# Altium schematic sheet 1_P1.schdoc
size 601 x 429 mm; Symbol: Sheet-Symbol_A4; Device: Sheet-Symbol_A4; Company: 嘉立创EDA; Version: V1.0; Page Size: A4; @Project Name: F407DCMI+AD9226; @Page Count: 1; @Update Date: 2024-08-18; @Create Date: 2024-08-13; @Schematic Name: Schematic1; @Page No: 1; @Page Name: P1; @Create Time: 14:49:27; @Update Time: 01:13:08; Width: 2338; Height: 1652; Region Start: 1; X Region Count: 6; Y Region Count: 4; Blade Width: 10; Title Block Position: 3; @Board Name: Board1
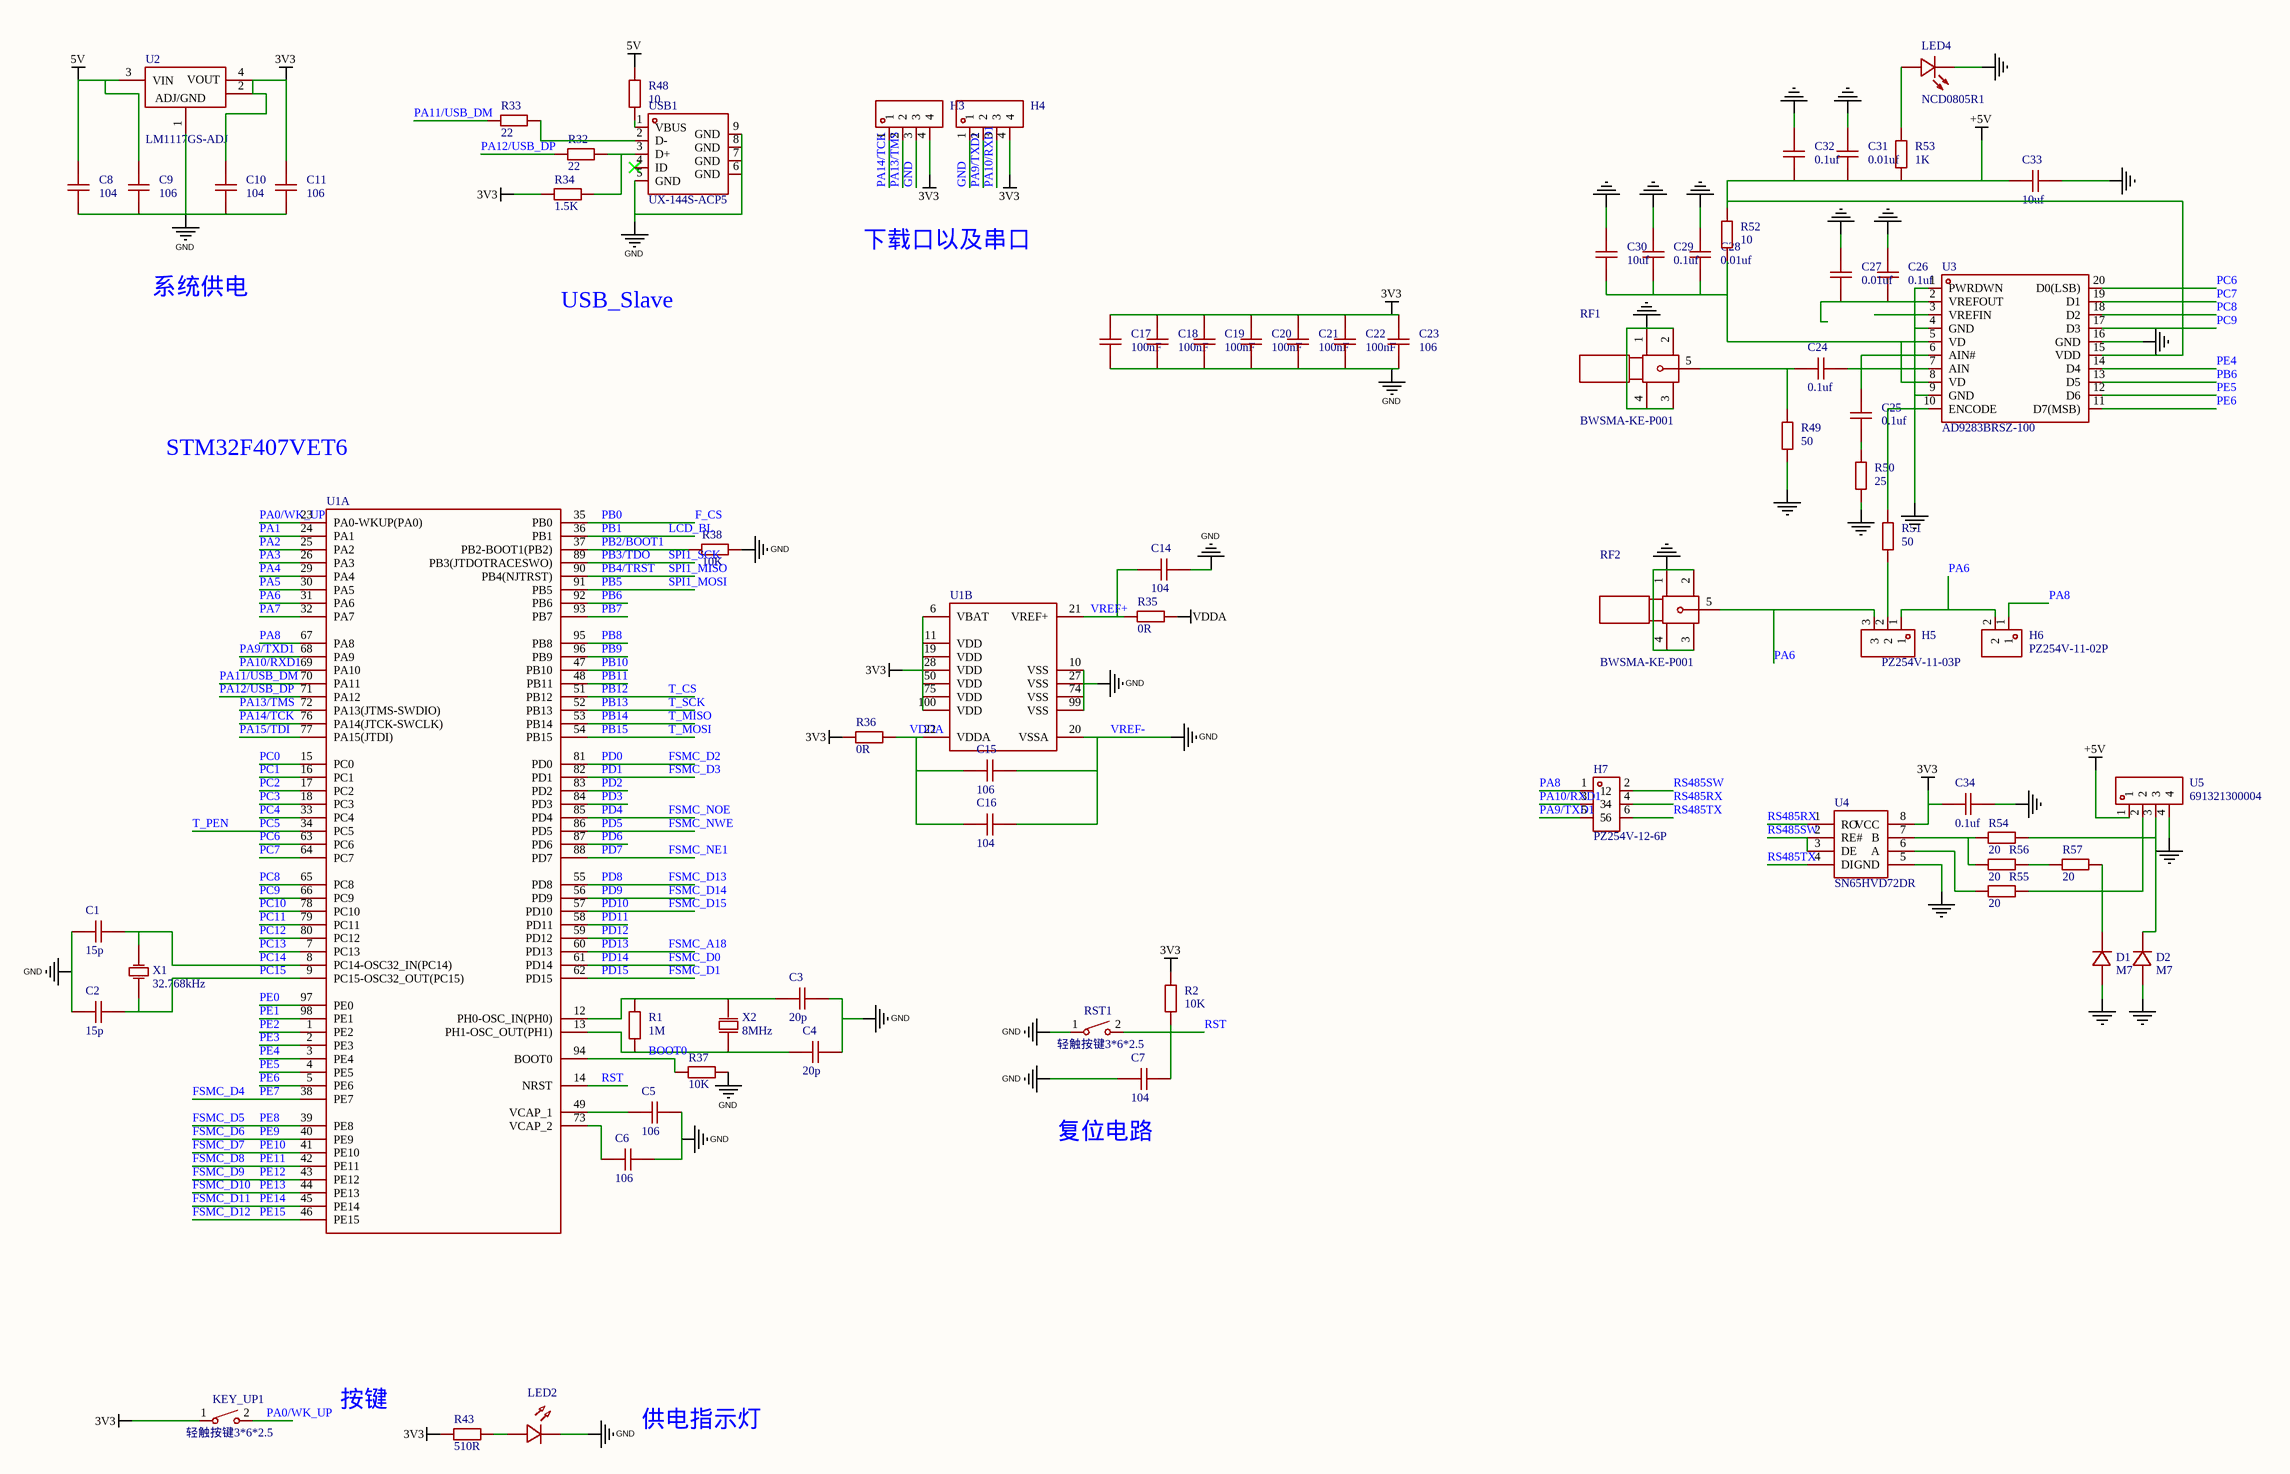
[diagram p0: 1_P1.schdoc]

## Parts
C1  15p  [C0805]  (value not drawn)
C2  15p  [C0805]  (value not drawn)
C3  20p  [C0805]  (value not drawn)
C4  20p  [C0805]  (value not drawn)
C5  106  [C0805]  (value not drawn)
C6  106  [C0805]  (value not drawn)
C7  104  [C0805]  (value not drawn)
C8  104  [C0805]  (value not drawn)
C9  106  [C0805]  (value not drawn)
C10  104  [C0805]  (value not drawn)
C11  106  [C0805]  (value not drawn)
C14  104  [C0805]  (value not drawn)
C15  106  [C0805]  (value not drawn)
C16  104  [C0805]  (value not drawn)
C17  100nF  [C0805]  (value not drawn)
C18  100nF  [C0805]  (value not drawn)
C19  100nF  [C0805]  (value not drawn)
C20  100nF  [C0805]  (value not drawn)
C21  100nF  [C0805]  (value not drawn)
C22  100nF  [C0805]  (value not drawn)
C23  106  [C0805]  (value not drawn)
C24  0.1uf  [C0805]  (value not drawn)
C25  0.1uf  [C0805]  (value not drawn)
C26  0.1uf  [C0805]  (value not drawn)
C27  0.01uf  [C0805]  (value not drawn)
C28  0.01uf  [C0805]  (value not drawn)
C29  0.1uf  [C0805]  (value not drawn)
C30  10uf  [C0805]  (value not drawn)
C31  0.01uf  [C0805]  (value not drawn)
C32  0.1uf  [C0805]  (value not drawn)
C33  10uf  [C0805]  (value not drawn)
C34  0.1uf  [C0805]  (value not drawn)
D1  M7  [SMA_L4.3-W2.6-LS5.2-RD]  (value not drawn)
D2  M7  [SMA_L4.3-W2.6-LS5.2-RD]  (value not drawn)
H3  2.54-1*4P反弯排针  [HDR-TH_4P-P2.54-H-M-W10.4]  (value not drawn)
H4  2.54-1*4P反弯排针  [HDR-TH_4P-P2.54-H-M-W10.4]  (value not drawn)
H5  PZ254V-11-03P  [HDR-TH_3P-P2.54-V-M]  (value not drawn)
H6  PZ254V-11-02P  [HDR-TH_2P-P2.54-V-M]  (value not drawn)
H7  PZ254V-12-6P  [HDR-TH_6P-P2.54-V-M-R2-C3-S2.54]  (value not drawn)
KEY_UP1  轻触按键3*6*2.5  [SW-SMD_L6.0-W3.6-LS8.0]  (value not drawn)
LED2  LED_0805-G  [LED_0805]  (value not drawn)
LED4  NCD0805R1  [LED0805-R-RD]  (value not drawn)
R1  1M  [R0805]  (value not drawn)
R2  10K  [R0805]  (value not drawn)
R32  22  [R0805]  (value not drawn)
R33  22  [R0805]  (value not drawn)
R34  1.5K  [R0805]  (value not drawn)
R35  0R  [R0805]  (value not drawn)
R36  0R  [R0805]  (value not drawn)
R37  10K  [R0805]  (value not drawn)
R38  10K  [R0805]  (value not drawn)
R43  510R  [R0805]  (value not drawn)
R48  10  [R0805]  (value not drawn)
R49  50  [R0805]  (value not drawn)
R50  25  [R0805]  (value not drawn)
R51  50  [R0805]  (value not drawn)
R52  10  [R0805]  (value not drawn)
R53  1K  [R0805]  (value not drawn)
R54  20  [R0805]  (value not drawn)
R55  20  [R0805]  (value not drawn)
R56  20  [R0805]  (value not drawn)
R57  20  [R0805]  (value not drawn)
RF1  BWSMA-KE-P001  [SMA-SMD_BWSMA-KE-P001]  (value not drawn)
RF2  BWSMA-KE-P001  [SMA-SMD_BWSMA-KE-P001]  (value not drawn)
RST1  轻触按键3*6*2.5  [SW-SMD_L6.0-W3.6-LS8.0]  (value not drawn)
U1  STM32F407VET6  [LQFP-100_L14.0-W14.0-P0.50-LS16.0-BL]  (value not drawn)  (parts A,B of 2)
U2  LM1117GS-ADJ  [SOT-223-3_L6.5-W3.4-P2.30-LS7.0-BR]  (value not drawn)
U3  AD9283BRSZ-100  [SSOP-20_L7.2-W5.3-P0.65-LS7.8-BL]  (value not drawn)
U4  SN65HVD72DR  [SOIC-8_L5.0-W4.0-P1.27-LS6.0-BL]  (value not drawn)
U5  691321300004  [CONN-TH_4P-P3.81_691321300004]  (value not drawn)
USB1  UX-144S-ACP5  [MINI-USB-SMD_UX-144S-ACP5]  (value not drawn)
X1  32.768kHz  [OSC-TH_BD3.1-P0.8-D0.3]  (value not drawn)
X2  8MHz  [CRYSTAL-SMD_L11.5-W4.8-LS12.7]  (value not drawn)

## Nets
3V3: C10.2 C11.2 C17.2 C18.2 C19.2 C20.2 C21.2 C22.2 C23.2 C34.1 H3.4 H4.4 KEY_UP1.1 R2.2 R34.1 R36.1 R43.1 U1.6(VBAT) U1.11(VDD) U1.19(VDD) U1.28(VDD) U1.50(VDD) U1.75(VDD) U1.100(VDD) U2.2(VOUT) U2.4(VOUT) U4.8(VCC)
5V: C8.2 C9.2 R48.1 U2.3(VIN)
+5V: C31.1 C32.1 C33.1 R52.2 R53.1 U3.15(VDD) U5.1
GND: C1.1 C2.1 C3.2 C4.2 C5.2 C6.2 C7.1 C8.1 C9.1 C10.1 C11.1 C14.2 C15.2 C16.2 C17.1 C18.1 C19.1 C20.1 C21.1 C22.1 C23.1 C26.2 C27.2 C28.2 C29.2 C30.2 C31.2 C32.2 C33.2 C34.2 D1.2(A) D2.2(A) H3.3 H4.1 LED2.1(C) LED4.2(-) R37.2 R38.2 R49.1 R50.1 RF1.1 RF1.2 RF1.3 RF1.4 RF2.1 RF2.2 RF2.3 RF2.4 RST1.1 U1.10(VSS) U1.20(VSSA) U1.27(VSS) U1.74(VSS) U1.99(VSS) U2.1(GND) U3.1(PWRDWN) U3.4(GND) U3.9(GND) U3.16(GND) U4.5(GND) U5.4 USB1.5(GND) USB1.6(GND) USB1.7(GND) USB1.8(GND) USB1.9(GND)  [also labelled VREF-]
VDDA: C15.1 C16.1 R35.2 R36.2 U1.22(VDDA)
BOOT0: R37.1 U1.94(BOOT0)
F_CS: U1.35(PB0)  [also labelled PB0]
FSMC_A18: U1.60(PD13)  [also labelled PD13]
FSMC_D0: U1.61(PD14)  [also labelled PD14]
FSMC_D1: U1.62(PD15)  [also labelled PD15]
FSMC_D2: U1.81(PD0)  [also labelled PD0]
FSMC_D3: U1.82(PD1)  [also labelled PD1]
FSMC_D4: U1.38(PE7)  [also labelled PE7]
FSMC_D5: U1.39(PE8)  [also labelled PE8]
FSMC_D6: U1.40(PE9)  [also labelled PE9]
FSMC_D7: U1.41(PE10)  [also labelled PE10]
FSMC_D8: U1.42(PE11)  [also labelled PE11]
FSMC_D9: U1.43(PE12)  [also labelled PE12]
FSMC_D10: U1.44(PE13)  [also labelled PE13]
FSMC_D11: U1.45(PE14)  [also labelled PE14]
FSMC_D12: U1.46(PE15)  [also labelled PE15]
FSMC_D13: U1.55(PD8)  [also labelled PD8]
FSMC_D14: U1.56(PD9)  [also labelled PD9]
FSMC_D15: U1.57(PD10)  [also labelled PD10]
FSMC_NE1: U1.88(PD7)  [also labelled PD7]
FSMC_NOE: U1.85(PD4)  [also labelled PD4]
FSMC_NWE: U1.86(PD5)  [also labelled PD5]
LCD_BL: U1.36(PB1)  [also labelled PB1]
PA0/WK_UP: KEY_UP1.2 U1.23(PA0-WKUP(PA0))
PA1: U1.24(PA1)
PA2: U1.25(PA2)
PA3: U1.26(PA3)
PA4: U1.29(PA4)
PA5: U1.30(PA5)
PA6: H5.1 H5.3 H6.2 RF2.5 U1.31(PA6)
PA7: U1.32(PA7)
PA8: H6.1 H7.1 U1.67(PA8)
PA9/TXD1: H4.2 H7.5 U1.68(PA9)
PA10/RXD1: H4.3 H7.3 U1.69(PA10)
PA11/USB_DM: R33.2 U1.70(PA11)
PA12/USB_DP: R32.1 U1.71(PA12)
PA13/TMS: H3.2 U1.72(PA13(JTMS-SWDIO))
PA14/TCK: H3.1 U1.76(PA14(JTCK-SWCLK))
PA15/TDI: U1.77(PA15(JTDI))
PB2/BOOT1: R38.1 U1.37(PB2-BOOT1(PB2))
PB3/TDO: U1.89(PB3(JTDOTRACESWO))  [also labelled SPI1_SCK]
PB4/TRST: U1.90(PB4(NJTRST))  [also labelled SPI1_MISO]
PB5: U1.91(PB5)  [also labelled SPI1_MOSI]
PB6: U1.92(PB6) U3.13(D5)
PB7: U1.93(PB7)
PB8: U1.95(PB8)
PB9: U1.96(PB9)
PB10: U1.47(PB10)
PB11: U1.48(PB11)
PB12: U1.51(PB12)  [also labelled T_CS]
PB13: U1.52(PB13)  [also labelled T_SCK]
PB14: U1.53(PB14)  [also labelled T_MISO]
PB15: U1.54(PB15)  [also labelled T_MOSI]
PC0: U1.15(PC0)
PC1: U1.16(PC1)
PC2: U1.17(PC2)
PC3: U1.18(PC3)
PC4: U1.33(PC4)
PC5: U1.34(PC5)  [also labelled T_PEN]
PC6: U1.63(PC6) U3.20(D0(LSB))
PC7: U1.64(PC7) U3.19(D1)
PC8: U1.65(PC8) U3.18(D2)
PC9: U1.66(PC9) U3.17(D3)
PC10: U1.78(PC10)
PC11: U1.79(PC11)
PC12: U1.80(PC12)
PC13: U1.7(PC13)
PC14: C1.2 U1.8(PC14-OSC32_IN(PC14)) X1.1(OSC1)
PC15: C2.2 U1.9(PC15-OSC32_OUT(PC15)) X1.2(OSC2)
PD2: U1.83(PD2)
PD3: U1.84(PD3)
PD6: U1.87(PD6)
PD11: U1.58(PD11)
PD12: U1.59(PD12)
PE0: U1.97(PE0)
PE1: U1.98(PE1)
PE2: U1.1(PE2)
PE3: U1.2(PE3)
PE4: U1.3(PE4) U3.14(D4)
PE5: U1.4(PE5) U3.12(D6)
PE6: U1.5(PE6) U3.11(D7(MSB))
RS485RX: H7.4 U4.1(RO)
RS485SW: H7.2 U4.2(RE#) U4.3(DE)
RS485TX: H7.6 U4.4(DI)
RST: C7.2 R2.1 RST1.2 U1.14(NRST)
VREF+: C14.1 R35.1 U1.21(VREF+)
NetC3_1: C3.1 R1.2 U1.12(PH0-OSC_IN(PH0)) X2.1(OSC1)
NetC4_1: C4.1 R1.1 U1.13(PH1-OSC_OUT(PH1)) X2.2(OSC2)
NetC5_1: C5.1 U1.49(VCAP_1)
NetC6_1: C6.1 U1.73(VCAP_2)
NetC24_1: C24.1 R49.2 RF1.5
NetC24_2: C24.2 U3.7(AIN)
NetC25_1: C25.1 R50.2
NetC25_2: C25.2 U3.6(AIN#)
NetC26_1: C26.1 C27.1 U3.2(VREFOUT)
NetC28_1: C28.1 C29.1 C30.1 R52.1 U3.5(VD) U3.8(VD)
NetD1_1: D1.1(K) R55.2 R57.2 U5.2
NetD2_1: D2.1(K) R54.1 U5.3
NetH5_2: H5.2 R51.1
NetLED2_2: LED2.2(A) R43.2
NetLED4_1: LED4.1(+) R53.2
NetR32_2: R32.2 R34.2 USB1.3(D+)
NetR33_1: R33.1 USB1.2(D-)
NetR48_2: R48.2 USB1.1(VBUS)
NetR51_2: R51.2 U3.10(ENCODE)
NetR54_2: R54.2 R56.2 U4.7(B)
NetR55_1: R55.1 U4.6(A)
NetR56_1: R56.1 R57.1

Not connected (* = marked no-connect by the designer): U3 3(VREFIN); USB1 4(ID)*

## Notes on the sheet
- 下载口以及串口
- 系统供电
- USB_Slave
- STM32F407VET6
- (near C7) 复位电路
- 按键
- 供电指示灯

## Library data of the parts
C1-C11 C14-C34 = CAP_0805: Symbol: CapAcitance; Convert to PCB: yes
D1 D2 = M7_C95872: 二极管配置:独立式;正向压降(Vf):1.1V@1A;直流反向耐压(Vr):1kV;整流电流:1A;; Manufacturer: MDD(辰达半导体); Add into BOM: yes; Diode Configuration: 独立式; Reverse Voltage (Vr): 1kV; Rectified Current: 1A; Reverse Leakage Current: 5uA@1kV
H3 H4 = 2.54-1*4P反弯排针: 间距:2.54mm;总PIN位数:4;排数:1;插针结构:1x4P;行距:-;安装类型:弯插;圆针/方针:方针;额定电流:3A;额定电压:-;配合针长度:6mm;塑高:-;端接针长度:-;触头材质:-;触头镀层:-;工作温度范围:-55~+105;颜色:黑色;; Manufacturer: BOOMELE(博穆精密); Add into BOM: yes; Pitch: 2.54mm; Pin Structure: 1x4P; Circluar Pins/Square Pins: 方针; Current Rating (Max): 3A
H5 = PZ254V-11-03P: 插针结构:1x3P;间距:2.54mm;行距:-;圆针/方针:方针;安装类型:直插;排数:单排;总PIN位数:3P;额定电流:3A;额定电压:250V;配合针长度:6mm;塑高:2.5mm;端接针长度:3mm;工作温度范围:-40℃~+105℃;颜色:黑色;; Manufacturer: XFCN(兴飞); Symbol: PZ254V-11-03P_C2937625; Add into BOM: yes; Pin Structure: 1x3P; Pitch: 2.54mm; Circluar Pins/Square Pins: 方针; Current Rating (Max): 3A; Voltage Rating (Max): 250V
H6 = PZ254V-11-02P: 插针结构:1x2P;间距:2.54mm;行距:-;圆针/方针:方针;安装类型:直插;排数:单排;总PIN位数:2P;额定电流:-;额定电压:-;配合针长度:6mm;塑高:2.5mm;端接针长度:3mm;触头材质:黄铜;触头镀层:-;工作温度范围:-40℃~+105℃;颜色:黑色;; Manufacturer: XFCN(兴飞); Add into BOM: yes; Pin Structure: 1x2P; Pitch: 2.54mm; Circluar Pins/Square Pins: 方针
H7 = PZ254V-12-6P: 插针结构:2x3P;间距:2.54mm;行距:2.54mm;圆针/方针:方针;安装类型:直插;排数:双排;总PIN位数:6P;额定电流:-;额定电压:-;配合针长度:6mm;塑高:2.5mm;端接针长度:3mm;触头材质:黄铜;触头镀层:-;工作温度范围:-40℃~+105℃;颜色:黑色;; Manufacturer: XFCN(兴飞); Add into BOM: yes; Pin Structure: 2x3P; Pitch: 2.54mm; Circluar Pins/Square Pins: 方针
KEY_UP1 RST1 = 轻触按键3*6*2.5: Add into BOM: yes
LED2 = LED_0805-G: Symbol: LED_G; Convert to PCB: yes
LED4 = NCD0805R1: 灯头类型:-;发光颜色:红色;正向电压(VF):1.6V~2.6V;功率:65mW;正向电流:20mA;主波长:615nm~630nm;二极管配置:独立二极管;透镜颜色:无色透明透镜;色温:-;发光强度:67mcd~195mcd;发光角度:130°;载带方式:-;工作温度:-30℃~+85℃;; Manufacturer: 国星光电; Symbol: FC-2012HRK-620D; Add into BOM: yes; Emitted Color: 红色; Power Dissipation: 65mW; Forward Current: 20mA; Diode Configuration: 独立二极管; Lens Color: 无色透明透镜; Viewing Angle: 130°
R1 R2 R32-R38 R43 R48 = Res_0805: Symbol: 电阻; Convert to PCB: yes
R49-R57 = RC0805FR-0710KL: 电阻类型:厚膜电阻;阻值:10kΩ;精度:±1%;功率:125mW;最大工作电压:150V;温度系数:±100ppm/℃;; Manufacturer: YAGEO(国巨); Add into BOM: yes; Tolerance: ±1%; Power(Watts): 125mW; Overload Voltage (Max): 150V
RF1 RF2 = BWSMA-KE-P001: 连接器类型:板端;接口类型:内孔;端口数量:1;接口直径:5.2mm;接口长度/高度:-;频率-最大值:-;射频系列:SMA;阻抗:50Ω;样式:偏脚;工作温度范围:-;; Manufacturer: BAT WIRELESS(蝙蝠无线); Add into BOM: yes; Connector Type: 板端; Interface Type: 内孔; Number of Ports: 1; Interface Diameter: 5.2mm; RF Series: SMA; Impedance: 50Ω; Style: 偏脚
U1 = STM32F407VET6: CPU内核:ARM Cortex-M4;CPU最大主频:168MHz;工作电压范围:1.8V~3.6V;程序存储容量:512KB;程序存储器类型:FLASH;RAM总容量:192KB;GPIO端口数量:82;; Manufacturer: ST(意法半导体); Add into BOM: yes; CPU Maximum Speed: 168MHz; Program Storage Size: 512KB; Program Memory Type: FLASH; RAM Size: 192KB; GPIO Ports Number: 82; ADC (Bit): 12bit; Universal Serial Bus: 有; Peripheral/Function: DMA；LCD/LED驱动；PWM
U2 = LM1117GS-ADJ: 输出类型:-;; Manufacturer: HTC; Add into BOM: yes
U3 = AD9283BRSZ-100: 接口:并行;电源电压:2.7V~3.6V;采样率:100MHz;分辨率:8位;; Manufacturer: ADI(亚德诺); Add into BOM: yes; Interface: 并行; differential input: 是; number of channels: 1; sampling frequency: 100MHz; resolution: 8位
U4 = SN65HVD72DR: 类型:收发器;数据速率:250Kbps;驱动器/接收器:1/1;; Manufacturer: TI(德州仪器); Add into BOM: yes; Types: 收发器; Supply Voltage: 3V~3.6V; Driver/receiver: 1/1
U5 = 691321300004: Add into BOM: yes
USB1 = UX-144S-ACP5: 连接器类型:Mini-B;标准:USB 2.0;公母:母;触点数量:5P;端口数量:1;安装方式:卧贴;额定电流 - 电源:1.5A;工作温度范围:-20℃~+70℃;焊接温度(最大值):260℃;; Manufacturer: XUNPU(讯普); Add into BOM: yes; Connector Type: Mini-B; Gender: 母; Number of Contacts: 5P; Number of Ports: 1; Current Rating - Power (Max): 1.5A; Welding Temperature (Max): 260℃
X1 = X308032768KGB2SC: 晶振类型:直插晶振;频率:32.768kHz;常温频差:±10ppm;外接负载电容:12.5pF;频率稳定度(全温):-;; Manufacturer: YXC(扬兴晶振); Add into BOM: yes; Crystal Type: 直插晶振; Normal temperature Frequency Tolerance: ±10ppm; External load capacitor: 12.5pF
X2 = X49SM8MSD2SC: 晶振类型:49SMD晶振;频率:8MHz;频率公差:±20ppm;负载电容:20pF;频率稳定度:±30ppm;; Manufacturer: YXC(扬兴晶振); Add into BOM: yes; Frequency Tolerance: ±20ppm; Load Capacitance: 20pF; Frequency Stability: ±30ppm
